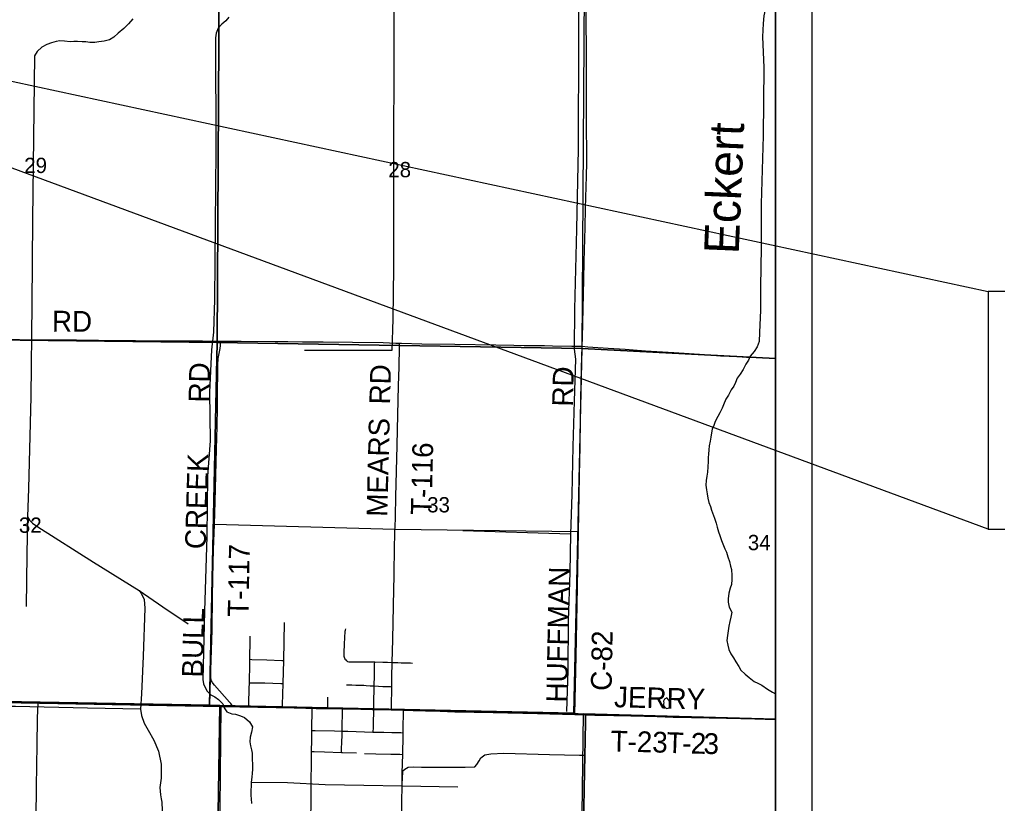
# Model space of a CAD drawing. Extents: x 0 to 39.4, y 0 to 22.
# Drawn here: x 6.833 to 9.507, y 15.083 to 17.227 of the extents above; entities that cross this region are included whole.
import ezdxf

# ---------------------------------------------------------------- set-up
doc = ezdxf.new("R2010")
doc.units = 0
for name, color, linetype in [('Default', 7, 'Continuous'), ('GM_X_City_Street', 7, 'Continuous'), ('GM_X_Corporation', 7, 'Continuous'), ('GM_X_County_Road', 7, 'Continuous'), ('GM_X_County_Road_Text', 7, 'Continuous'), ('GM_X_Interstate_Route', 7, 'Continuous'), ('GM_X_Minor_Lake', 7, 'Continuous'), ('GM_X_Minor_River', 7, 'Continuous'), ('GM_X_Minor_River_Text', 7, 'Continuous'), ('GM_X_Rail_Line', 7, 'Continuous'), ('GM_X_Section', 7, 'Continuous'), ('GM_X_Section_Text', 7, 'Continuous'), ('GM_X_Township_Road', 7, 'Continuous'), ('GM_X_Township_Road_Text', 7, 'Continuous'), ('SH_Data', 7, 'Continuous')]:
    doc.layers.add(name, color=color, linetype=linetype)

msp = doc.modelspace()

# ---------------------------------------------------------------- linework, layer by layer
at = {"layer": 'Default'}
for points in [[(8.9, 16.3001), (8.9, 17.2957), (8.3769, 17.3064), (8.3707, 16.3273)], [(8.9, 15.3135), (8.9, 16.3001), (8.3707, 16.3273), (8.348, 15.3299), (8.3745, 15.3277)], [(8.9, 14.3437), (8.9, 15.3135), (8.3745, 15.3277), (8.3619, 14.3697)]]:
    msp.add_lwpolyline(points, close=True, dxfattribs=at)
at = {"layer": 'GM_X_City_Street'}
for points in [[(7.5517, 15.3454), (7.5519, 15.353), (7.5535, 15.4108), (7.5553, 15.4738), (7.5568, 15.5255), (7.5573, 15.578)], [(7.7238, 15.4764), (7.7223, 15.4792), (7.7213, 15.4822), (7.7209, 15.4852), (7.7207, 15.4884), (7.7209, 15.4979), (7.7214, 15.5169), (7.7221, 15.539), (7.723, 15.551), (7.7234, 15.5538), (7.7241, 15.5568), (7.7252, 15.5603)], [(7.4596, 15.3477), (7.4598, 15.3567), (7.4608, 15.3973), (7.4612, 15.413), (7.4627, 15.4658), (7.4628, 15.4771), (7.4634, 15.5309), (7.4636, 15.5403)], [(7.4628, 15.4771), (7.4678, 15.477), (7.5089, 15.4757), (7.5497, 15.4741), (7.5553, 15.4738)], [(7.7238, 15.4764), (7.7258, 15.4741), (7.7276, 15.4726), (7.7299, 15.4714), (7.7331, 15.4707), (7.7355, 15.4703), (7.7393, 15.47), (7.7485, 15.4699), (7.7647, 15.4705), (7.8005, 15.4704), (7.8042, 15.4702), (7.8268, 15.4695), (7.8393, 15.4691), (7.8517, 15.4687), (7.8571, 15.4685), (7.8675, 15.4682), (7.8767, 15.4679), (7.8875, 15.4676), (7.8935, 15.4674), (7.898, 15.4672), (7.902, 15.4671), (7.9079, 15.4669)], [(7.8013, 15.34), (7.8014, 15.3451), (7.8017, 15.3617), (7.8025, 15.3977), (7.8026, 15.4044), (7.8032, 15.4327), (7.804, 15.464), (7.8042, 15.4702)], [(7.4146, 15.3485), (7.4144, 15.3492), (7.4138, 15.3511), (7.4134, 15.3522), (7.4128, 15.3535), (7.4106, 15.3564), (7.4072, 15.3602), (7.366, 15.4063), (7.3621, 15.4111), (7.3603, 15.4136), (7.3591, 15.4157), (7.3578, 15.4185), (7.3568, 15.4215), (7.3561, 15.4251)], [(7.4612, 15.413), (7.4661, 15.4129), (7.5036, 15.4124), (7.5474, 15.411), (7.5535, 15.4108)], [(7.7266, 15.4078), (7.7326, 15.4075), (7.7417, 15.4071), (7.7526, 15.4068), (7.7593, 15.4066), (7.7676, 15.4063), (7.7746, 15.406), (7.7812, 15.4056), (7.7914, 15.405), (7.7971, 15.4046), (7.8026, 15.4044), (7.8143, 15.4035), (7.8267, 15.403), (7.8475, 15.4024), (7.8506, 15.4023)], [(7.6758, 15.3424), (7.6757, 15.3611), (7.6756, 15.3734)], [(7.6313, 15.2248), (7.6317, 15.2568), (7.6318, 15.2749), (7.6318, 15.2828), (7.6319, 15.2862), (7.6324, 15.3071), (7.6328, 15.3192), (7.6333, 15.3374), (7.6335, 15.3433)], [(7.7131, 15.2225), (7.7133, 15.2262), (7.7137, 15.235), (7.7143, 15.2474), (7.7149, 15.2723), (7.715, 15.2806), (7.7154, 15.2971), (7.7161, 15.3282), (7.7162, 15.3344), (7.7162, 15.3418)], [(7.8002, 15.2782), (7.8003, 15.2817), (7.8004, 15.2872), (7.8005, 15.2925), (7.8008, 15.3096), (7.8013, 15.3289), (7.8013, 15.34)], [(7.6318, 15.2828), (7.6357, 15.2827), (7.6413, 15.2824), (7.6937, 15.2811), (7.715, 15.2806), (7.7308, 15.2802), (7.7987, 15.2782), (7.8002, 15.2782), (7.8293, 15.2776), (7.8513, 15.2772), (7.8757, 15.2767), (7.8819, 15.2765)], [(7.6313, 15.2248), (7.6383, 15.2246), (7.6666, 15.2238), (7.7131, 15.2225), (7.7162, 15.2224), (7.7539, 15.2214)], [(7.776, 15.2196), (7.8073, 15.2187), (7.8478, 15.2178), (7.8728, 15.2173), (7.8807, 15.2171)]]:
    msp.add_lwpolyline(points, dxfattribs=at)
at = {"layer": 'GM_X_Corporation'}
msp.add_lwpolyline([(8.3729, 14.874), (7.8752, 14.8925), (7.6264, 14.9016), (7.3784, 14.9119), (7.3814, 15.0704), (7.3845, 15.3493), (7.3532, 15.3504), (7.3553, 15.4266), (7.3626, 15.7535), (7.3656, 15.8466), (7.8594, 15.8328), (8.3606, 15.827), (8.3571, 15.626), (8.3542, 15.4855), (8.3506, 15.3268), (8.3806, 15.3258), (8.3806, 15.3081), (8.3795, 15.2552), (8.3776, 15.1713), (8.3767, 15.1247), (8.3759, 15.0687), (8.3749, 14.9972), (8.3738, 14.9443), (8.373, 14.8915)], close=True, dxfattribs=at)
at = {"layer": 'GM_X_County_Road'}
msp.add_line((8.3808, 15.3252), (8.3514, 15.3259), dxfattribs=at)
for points in [[(8.3715, 16.3333), (8.3721, 16.3573), (8.3759, 16.5157), (8.377, 16.5654), (8.3794, 16.6586), (8.381, 16.7114), (8.3832, 16.7984), (8.3843, 16.8357), (8.3844, 16.8668), (8.3837, 16.9289), (8.3834, 16.9849), (8.3834, 17.0843), (8.3832, 17.1589), (8.3826, 17.2086), (8.3825, 17.2801), (8.3824, 17.3006)], [(8.3611, 15.8262), (8.3623, 15.8756), (8.3633, 15.9254), (8.3643, 15.9813), (8.3661, 16.059), (8.3672, 16.1335), (8.3683, 16.1895), (8.37, 16.2734), (8.3715, 16.3333)], [(8.3514, 15.3259), (8.3517, 15.3541), (8.3526, 15.3944), (8.355, 15.5154), (8.3561, 15.5557), (8.3571, 15.6053), (8.3575, 15.6457), (8.3584, 15.6922), (8.3594, 15.7449), (8.3611, 15.8262)], [(8.3731, 14.8735), (8.3732, 14.8909), (8.374, 14.9438), (8.3751, 14.9966), (8.3761, 15.0681), (8.3769, 15.1241), (8.3779, 15.1707), (8.3797, 15.2547), (8.3809, 15.3075), (8.3808, 15.3252)]]:
    msp.add_lwpolyline(points, dxfattribs=at)
at = {"layer": 'GM_X_Interstate_Route'}
for points in [[(6.7816, 15.3608), (6.8686, 15.3598), (6.8838, 15.3595), (6.9121, 15.359), (6.9743, 15.3577), (7.0303, 15.3567), (7.1267, 15.3547), (7.2042, 15.3533), (7.2477, 15.3526), (7.2944, 15.352), (7.3534, 15.3507), (7.3843, 15.3498), (7.3967, 15.3493), (7.4144, 15.349), (7.4525, 15.3485), (7.4593, 15.3483), (7.4773, 15.3477), (7.5048, 15.3472), (7.5514, 15.346), (7.5601, 15.3457), (7.5871, 15.3451), (7.6158, 15.3445), (7.6332, 15.3438), (7.6441, 15.3434), (7.6756, 15.343), (7.716, 15.3424), (7.7321, 15.3421), (7.7662, 15.3412), (7.7972, 15.3406), (7.8011, 15.3405), (7.8219, 15.3401), (7.8494, 15.3394), (7.8825, 15.3385), (7.9087, 15.3378), (7.9428, 15.3367), (7.9831, 15.3355), (8.0234, 15.3344), (8.1283, 15.332), (8.2492, 15.3291), (8.3512, 15.3264), (8.3806, 15.3258), (8.4059, 15.3252), (8.4366, 15.3245), (8.4584, 15.324), (8.505, 15.3229), (8.5423, 15.3219), (8.5765, 15.321), (8.62, 15.3199), (8.7194, 15.3173), (8.766, 15.3163), (8.8437, 15.3144), (8.9, 15.3132), (8.9, 20.9)], [(8.9, 14.1), (8.9, 15.3132), (8.8437, 15.3144), (8.766, 15.3163), (8.7194, 15.3173), (8.62, 15.3199), (8.5765, 15.321), (8.5423, 15.3219), (8.505, 15.3229), (8.4584, 15.324), (8.4366, 15.3245), (8.4059, 15.3252), (8.3806, 15.3258), (8.3512, 15.3264), (8.2492, 15.3291), (8.1283, 15.332), (8.0234, 15.3344), (7.9831, 15.3355), (7.9428, 15.3367), (7.9087, 15.3378), (7.8825, 15.3385), (7.8494, 15.3394), (7.8219, 15.3401), (7.8011, 15.3405), (7.7972, 15.3406), (7.7662, 15.3412), (7.7321, 15.3421), (7.716, 15.3424), (7.6756, 15.343), (7.6441, 15.3434), (7.6332, 15.3438), (7.6158, 15.3445), (7.5871, 15.3451), (7.5601, 15.3457), (7.5514, 15.346), (7.5048, 15.3472), (7.4773, 15.3477), (7.4593, 15.3483), (7.4525, 15.3485), (7.4144, 15.349), (7.3967, 15.3493), (7.3843, 15.3498), (7.3534, 15.3507), (7.2944, 15.352), (7.2477, 15.3526), (7.2042, 15.3533), (7.1267, 15.3547), (7.0303, 15.3567), (6.9743, 15.3577), (6.9121, 15.359), (6.8838, 15.3595), (6.8686, 15.3598), (6.7816, 15.3608)]]:
    msp.add_lwpolyline(points, dxfattribs=at)
at = {"layer": 'GM_X_Minor_Lake'}
msp.add_line((8.595, 15.3575), (8.5945, 15.3552), dxfattribs=at)
msp.add_lwpolyline([(8.5945, 15.3552), (8.5945, 15.351), (8.5974, 15.3453), (8.6031, 15.3429), (8.6069, 15.3436), (8.6107, 15.3454), (8.6109, 15.3553), (8.6106, 15.3625), (8.6054, 15.3702), (8.6032, 15.3714), (8.5967, 15.3681), (8.5943, 15.3624), (8.595, 15.3575)], dxfattribs=at)
at = {"layer": 'GM_X_Minor_River'}
for points in [[(8.3796, 18.2246), (8.3733, 18.0063), (8.3771, 17.8061), (8.3703, 17.5605), (8.3638, 17.3741), (8.3593, 17.316), (8.3618, 17.2848), (8.3616, 17.1762), (8.3606, 16.8731), (8.3565, 16.6533), (8.3505, 16.4353), (8.3496, 16.3256), (8.3537, 16.2978), (8.35, 16.1835), (8.3462, 16.0594), (8.343, 15.9276), (8.3395, 15.8198), (8.3375, 15.715), (8.3335, 15.5829), (8.3325, 15.4465), (8.3289, 15.3345)], [(7.872, 17.9555), (7.8691, 17.8199), (7.8643, 17.6422), (7.8609, 17.5006), (7.8572, 17.3826), (7.8568, 17.3024), (7.8562, 17.1041), (7.8559, 16.8838), (7.8556, 16.7266), (7.8557, 16.5477), (7.8535, 16.4075), (7.8507, 16.3214), (7.7334, 16.322), (7.6118, 16.3215)], [(8.9, 17.9539), (8.892, 17.6933), (8.8804, 17.4903), (8.8779, 17.3357), (8.8786, 17.2856), (8.876, 17.2704), (8.8686, 17.2371), (8.8671, 17.2166), (8.8652, 17.1794), (8.8683, 17.0958), (8.8668, 16.9093), (8.8612, 16.7229), (8.861, 16.6036), (8.8598, 16.4958), (8.8594, 16.4323), (8.8568, 16.3709), (8.856, 16.3469)], [(7.1424, 17.2292), (7.1304, 17.215), (7.1176, 17.2023), (7.1025, 17.1897), (7.0902, 17.1785), (7.0786, 17.1719), (7.0645, 17.1683), (7.0497, 17.1659), (7.0382, 17.1642), (7.0246, 17.1645), (7.014, 17.1658), (7.0037, 17.1664), (6.9912, 17.167), (6.9813, 17.1672), (6.9714, 17.1662), (6.9559, 17.1684), (6.943, 17.169), (6.9331, 17.1673), (6.9197, 17.1634), (6.9075, 17.159), (6.894, 17.1513), (6.8809, 17.1401), (6.8738, 17.1281)], [(7.4055, 17.2337), (7.3969, 17.224), (7.3861, 17.2147), (7.376, 17.2035), (7.3705, 17.1899), (7.3683, 17.177)], [(7.3683, 17.177), (7.3693, 16.8701), (7.3661, 16.4617), (7.3634, 16.3721), (7.3575, 16.3236), (7.3524, 16.2082), (7.3542, 16.0749), (7.3472, 15.9781), (7.3446, 15.8144), (7.3386, 15.6087), (7.3341, 15.4222)], [(6.8738, 17.1281), (6.8682, 16.68), (6.8658, 16.4487), (6.8633, 16.195), (6.8575, 15.944), (6.8546, 15.867), (6.8527, 15.7626), (6.8508, 15.6213)], [(8.856, 16.3469), (8.8504, 16.3318), (8.8418, 16.3191), (8.8313, 16.306), (8.8265, 16.2954), (8.8195, 16.2845), (8.8116, 16.2699), (8.8038, 16.2575), (8.796, 16.2466), (8.7912, 16.2345), (8.7865, 16.2247), (8.7795, 16.2142), (8.7716, 16.1995), (8.7642, 16.1887), (8.7586, 16.1736), (8.7542, 16.1638), (8.7479, 16.1513), (8.7424, 16.1412), (8.7357, 16.128), (8.7314, 16.1171), (8.7274, 16.1065), (8.7249, 16.0963), (8.7236, 16.0845), (8.7218, 16.0739), (8.7193, 16.0611), (8.718, 16.0504), (8.7174, 16.0387), (8.7165, 16.0288), (8.7163, 16.0182), (8.7156, 16.0034), (8.7146, 15.9894), (8.7125, 15.978), (8.7112, 15.9666), (8.7102, 15.9537), (8.7118, 15.9404), (8.7132, 15.9301), (8.7152, 15.9183), (8.7181, 15.9065), (8.7224, 15.895), (8.7253, 15.8855), (8.7333, 15.8633), (8.738, 15.8499), (8.7412, 15.8384), (8.7444, 15.8255), (8.7484, 15.8155), (8.7531, 15.8025), (8.7559, 15.793), (8.7614, 15.7796), (8.7662, 15.77), (8.7697, 15.7578), (8.7744, 15.7444), (8.7773, 15.7322), (8.7801, 15.7226), (8.7814, 15.7067), (8.7812, 15.6953), (8.7798, 15.6816), (8.7766, 15.6718), (8.7729, 15.6578), (8.7711, 15.643), (8.7709, 15.6335), (8.7733, 15.6202), (8.7811, 15.6064), (8.7785, 15.592), (8.7757, 15.581), (8.7732, 15.5674), (8.7707, 15.5553), (8.7689, 15.542), (8.7675, 15.5288), (8.7696, 15.5154), (8.7728, 15.504), (8.7786, 15.4921), (8.7853, 15.481), (8.7915, 15.4702), (8.8001, 15.4571), (8.806, 15.4472), (8.8175, 15.4363), (8.8284, 15.427), (8.8423, 15.4161), (8.8521, 15.4121), (8.863, 15.4066), (8.8787, 15.3953), (8.8919, 15.3871), (8.9, 15.3829)], [(6.8546, 15.867), (6.8597, 15.8581), (6.8679, 15.8496), (6.8826, 15.8399), (7.035, 15.7425), (7.1597, 15.6654), (7.2246, 15.6206), (7.294, 15.5745)], [(8.3395, 15.8198), (8.0456, 15.829)], [(7.1597, 15.6654), (7.166, 15.6566), (7.1733, 15.6409), (7.1751, 15.6169), (7.1704, 15.4859), (7.1666, 15.3827), (7.1639, 15.3406), (7.1663, 15.3238), (7.1739, 15.3028), (7.1841, 15.2836), (7.2003, 15.2563), (7.2125, 15.2262), (7.2204, 15.1903), (7.2197, 15.1523), (7.2166, 15.1265), (7.2185, 15.1064), (7.2202, 15.0957), (7.2219, 15.0865)], [(7.3341, 15.4222), (7.3358, 15.4097), (7.3406, 15.4001), (7.3461, 15.3901), (7.3562, 15.3797), (7.3671, 15.3745), (7.3772, 15.3671), (7.3888, 15.3551), (7.3924, 15.3441), (7.3998, 15.3333), (7.413, 15.3281), (7.4236, 15.3268), (7.4368, 15.3228), (7.4481, 15.3176), (7.4616, 15.306), (7.4697, 15.2922), (7.4668, 15.2782), (7.4639, 15.2645), (7.4629, 15.2516), (7.4646, 15.2406), (7.4675, 15.2295), (7.4688, 15.22), (7.4689, 15.2025), (7.4698, 15.1911), (7.4699, 15.1755), (7.4686, 15.1653), (7.4684, 15.155), (7.4659, 15.1414), (7.466, 15.1293), (7.4655, 15.1198), (7.4652, 15.105), (7.4662, 15.0954), (7.4675, 15.0829)], [(7.1639, 15.3406), (7.0181, 15.3432), (6.8218, 15.3479), (6.7644, 15.3482)], [(7.8788, 15.1315), (7.8797, 15.1577), (7.8809, 15.1642), (7.8814, 15.1718), (7.8861, 15.1766), (7.8953, 15.1822), (7.909, 15.1827), (7.9318, 15.1822), (8.0514, 15.182), (8.0784, 15.1834), (8.0839, 15.1894), (8.0894, 15.1999), (8.0948, 15.2081), (8.1052, 15.2155), (8.122, 15.2187), (8.157, 15.2203), (8.2819, 15.2165), (8.3639, 15.215), (8.3791, 15.2147), (8.3767, 15.1229), (8.3765, 15.0727)], [(7.4659, 15.1414), (7.5652, 15.1399), (7.6684, 15.1346), (7.7747, 15.1327), (7.8788, 15.1315), (8.0314, 15.128)], [(7.2219, 15.0865), (7.2291, 14.9098)]]:
    msp.add_lwpolyline(points, dxfattribs=at)
at = {"layer": 'GM_X_Rail_Line'}
msp.add_lwpolyline([(5.6226, 15.3806), (5.8907, 15.3757), (7.6341, 15.3434)], dxfattribs=at)
at = {"layer": 'GM_X_Section'}
for points in [[(7.3784, 17.3348), (7.3732, 16.344), (6.3716, 16.3557), (6.3887, 17.3403)], [(8.3769, 17.3064), (8.3707, 16.3273), (7.3732, 16.344), (7.3784, 17.3348)], [(6.3716, 16.3557), (7.3732, 16.344), (7.3525, 15.3518), (6.3741, 15.3693), (6.3442, 15.3693), (6.3626, 15.7927)], [(8.3707, 16.3273), (8.348, 15.3299), (7.3801, 15.3507), (7.3525, 15.3518), (7.3732, 16.344)], [(6.3741, 15.3693), (7.3525, 15.3518), (7.3801, 15.3507), (7.3661, 14.4082), (6.3684, 14.4076)], [(8.348, 15.3299), (8.3745, 15.3277), (8.3619, 14.3697), (7.3661, 14.4082), (7.3801, 15.3507)]]:
    msp.add_lwpolyline(points, close=True, dxfattribs=at)
at = {"layer": 'GM_X_Township_Road'}
for p, q in [((7.3536, 15.3501), (7.3845, 15.3493)), ((7.3989, 15.3487), (7.4146, 15.3485)), ((7.6758, 15.3424), (7.7162, 15.3418)), ((7.8497, 15.3388), (7.8827, 15.338)), ((8.3514, 15.3259), (8.3808, 15.3252))]:
    msp.add_line(p, q, dxfattribs=at)
for points in [[(6.374, 16.3582), (6.4038, 16.3573), (6.4846, 16.3562), (6.6307, 16.3545), (6.6805, 16.3541), (6.7209, 16.3534), (6.7986, 16.3524), (6.867, 16.3514), (6.9882, 16.3506), (7.1095, 16.3495), (7.1499, 16.349), (7.24, 16.3485), (7.296, 16.3482), (7.3333, 16.3482), (7.3706, 16.3477), (7.3829, 16.3475)], [(7.3658, 15.8461), (7.3677, 15.9087), (7.3716, 16.0516), (7.3728, 16.1137), (7.3737, 16.1666), (7.3743, 16.2132), (7.375, 16.2567), (7.3754, 16.2878), (7.3758, 16.2946), (7.3763, 16.3001), (7.3777, 16.3093), (7.3812, 16.3274), (7.3821, 16.3355), (7.3829, 16.3475)], [(7.3829, 16.3475), (7.3986, 16.3473), (7.439, 16.3472), (7.5323, 16.3465), (7.5665, 16.3463), (7.6069, 16.3457), (7.6628, 16.3453), (7.7437, 16.3444), (7.8276, 16.3433), (7.8618, 16.3423), (7.872, 16.342)], [(7.8597, 15.8363), (7.8607, 15.8691), (7.862, 15.9219), (7.8654, 16.0617), (7.8665, 16.1052), (7.8696, 16.2263), (7.8708, 16.276), (7.8721, 16.3319), (7.872, 16.3393), (7.872, 16.342)], [(7.872, 16.342), (7.8773, 16.3418), (7.9333, 16.3404), (8.0234, 16.3389), (8.1353, 16.337), (8.185, 16.3361), (8.213, 16.3358), (8.2348, 16.3357), (8.2503, 16.3357), (8.2689, 16.3351), (8.2907, 16.3345), (8.3435, 16.3341), (8.3652, 16.3337), (8.3715, 16.3333)], [(8.3715, 16.3333), (8.3868, 16.3322), (8.4426, 16.3282), (8.4891, 16.3251), (8.5108, 16.3236), (8.5449, 16.3211), (8.6225, 16.3164), (8.7062, 16.3105), (8.7496, 16.3076), (8.7962, 16.3052), (8.821, 16.3037), (8.8489, 16.3024), (8.8675, 16.302), (8.8799, 16.3015), (8.8954, 16.3007), (8.9, 16.3006)], [(7.3561, 15.4251), (7.356, 15.4262), (7.3556, 15.4324), (7.356, 15.4479), (7.3592, 15.5566), (7.3608, 15.6498), (7.3625, 15.743), (7.3645, 15.8051), (7.3657, 15.8444), (7.3658, 15.8461)], [(7.8517, 15.4687), (7.8534, 15.531), (7.8546, 15.5777), (7.856, 15.6679), (7.8569, 15.7052), (7.8573, 15.7193), (7.8595, 15.8282), (7.8596, 15.8322), (7.8597, 15.8363)], [(7.8506, 15.4023), (7.8507, 15.4075), (7.851, 15.427), (7.8511, 15.4349), (7.8515, 15.4627), (7.8517, 15.4687)], [(7.8497, 15.3388), (7.8498, 15.3443), (7.8499, 15.3548), (7.8506, 15.395), (7.8506, 15.4023)], [(6.3805, 15.3681), (6.4151, 15.3672), (6.4648, 15.3662), (6.502, 15.3653), (6.5269, 15.3649), (6.5642, 15.364), (6.6326, 15.3625), (6.6854, 15.3614), (6.7258, 15.3611), (6.7818, 15.3602), (6.8689, 15.3593), (6.884, 15.359)], [(6.8685, 14.4122), (6.8685, 14.4182), (6.8698, 14.5084), (6.8705, 14.5488), (6.8708, 14.5757), (6.8716, 14.6282), (6.8722, 14.6692), (6.8742, 14.7967), (6.8762, 14.9336), (6.8771, 14.9895), (6.8777, 15.0424), (6.879, 15.1294), (6.8802, 15.1854), (6.881, 15.2445), (6.8822, 15.3129), (6.883, 15.3409), (6.8837, 15.3533), (6.884, 15.359)], [(6.884, 15.359), (6.9124, 15.3584), (6.9746, 15.3572), (7.0305, 15.3561), (7.1269, 15.3541), (7.2045, 15.3527), (7.248, 15.352), (7.2946, 15.3515), (7.3536, 15.3501)], [(7.3845, 15.3493), (7.3969, 15.3487), (7.3989, 15.3487)], [(7.4146, 15.3485), (7.4527, 15.348), (7.4596, 15.3477)], [(7.4596, 15.3477), (7.4775, 15.3472), (7.5051, 15.3466), (7.5517, 15.3454)], [(7.5517, 15.3454), (7.5604, 15.3452), (7.5873, 15.3446), (7.616, 15.3439), (7.6335, 15.3433)], [(7.6335, 15.3433), (7.6443, 15.3429), (7.6758, 15.3424)], [(7.7162, 15.3418), (7.7323, 15.3415), (7.7664, 15.3407), (7.7974, 15.34), (7.8013, 15.34)], [(7.8013, 15.34), (7.8222, 15.3395), (7.8497, 15.3388)], [(7.8819, 15.2765), (7.8824, 15.294), (7.8824, 15.302), (7.8826, 15.3195), (7.8827, 15.338)], [(7.8827, 15.338), (7.9089, 15.3373), (7.943, 15.3361), (7.9833, 15.3349), (8.0236, 15.3339), (8.1285, 15.3315), (8.2494, 15.3285), (8.3514, 15.3259)], [(8.3808, 15.3252), (8.4062, 15.3246), (8.4369, 15.324), (8.4586, 15.3234), (8.5052, 15.3224), (8.5425, 15.3213), (8.5767, 15.3204), (8.6202, 15.3193), (8.7196, 15.3168), (8.7662, 15.3158), (8.8439, 15.3139), (8.9, 15.3126)], [(7.8807, 15.2171), (7.8808, 15.2255), (7.8818, 15.2597), (7.8819, 15.2765)], [(7.6266, 14.901), (7.6282, 14.985), (7.6301, 15.0905), (7.6307, 15.1526), (7.6309, 15.1836), (7.6313, 15.2165), (7.6313, 15.2248)], [(7.8755, 14.891), (7.8755, 14.8919), (7.8761, 14.9362), (7.8785, 15.0824), (7.8794, 15.1353), (7.8796, 15.1664), (7.8807, 15.2171)]]:
    msp.add_lwpolyline(points, dxfattribs=at)
at = {"layer": 'SH_Data'}
for p, q in [((9, 21), (9, 14)), ((8.9, 20.9), (8.9, 14.1))]:
    msp.add_line(p, q, dxfattribs=at)
for points in [[(9.482, 15.8329), (5.273, 17.39), (9.482, 16.4829)], [(9.482, 15.8329), (10.952, 15.8329), (10.952, 16.4829), (9.482, 16.4829)]]:
    msp.add_lwpolyline(points, close=True, dxfattribs=at)

# ---------------------------------------------------------------- texts
at = {"layer": 'GM_X_County_Road_Text'}
for s, rotation, p in [('RD', 88.5175, (8.3461, 16.1678)), ('HUFFMAN', 88.8791, (8.3302, 15.3585)), ('C-82', 88.9714, (8.4521, 15.3905))]:
    msp.add_text(s, height=0.05682, rotation=rotation, dxfattribs=at).set_placement(p)
at = {"layer": 'GM_X_Minor_River_Text'}
msp.add_text('Eckert', height=0.09476, rotation=87.581, dxfattribs=at).set_placement((8.7996, 16.5843))
at = {"layer": 'GM_X_Section_Text'}
for s, p in [('29', (6.8455, 16.8073)), ('28', (7.8413, 16.7957)), ('33', (7.9476, 15.879)), ('32', (6.8309, 15.8232)), ('34', (8.8247, 15.7757))]:
    msp.add_text(s, height=0.04186, rotation=0, dxfattribs=at).set_placement(p)
at = {"layer": 'GM_X_Township_Road_Text'}
for s, height, rotation, p in [('RD', 0.05682, 359.5064, (6.9211, 16.3738)), ('RD', 0.05682, 89.0047, (7.3519, 16.1791)), ('RD', 0.05682, 88.5194, (7.8461, 16.1737)), ('MEARS', 0.05682, 88.6033, (7.8386, 15.8666)), ('T-116', 0.05682, 88.6098, (7.9595, 15.8713)), ('CREEK', 0.05682, 88.3806, (7.3419, 15.7778)), ('T-117', 0.05682, 88.8908, (7.4587, 15.5931)), ('BULL', 0.05682, 88.6947, (7.3336, 15.4269)), ('JERRY', 0.05682, 358.4392, (8.4583, 15.3463)), ('T-23', 0.05682, 358.5851, (8.4488, 15.2254)), ('T', 0.0568, 358.0239, (8.6015, 15.2213)), ('2', 0.0568, 358.8031, (8.6682, 15.2193)), ('3', 0.0568, 358.828, (8.7032, 15.2186)), ('-', 0.0568, 358.7216, (8.6447, 15.2199))]:
    msp.add_text(s, height=height, rotation=rotation, dxfattribs=at).set_placement(p)

doc.saveas('drawing.dxf')
